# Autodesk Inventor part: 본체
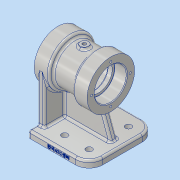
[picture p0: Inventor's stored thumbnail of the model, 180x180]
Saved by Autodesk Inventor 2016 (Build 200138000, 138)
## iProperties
Created: 2020-06
Part Number: 본체
Material: 알루미늄 6061
Document SubType Name: Modeling
Designer: 605-12
Density: 2.7 g/cm^3
Appearance: 알루미늄 - 평지
Mass: 724.958 g
Surface Area: 642.533 cm^2
Volume: 268.503 cm^3
Author: 605-12
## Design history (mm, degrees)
sketch "스케치1"
  geometry: L1 (-45, 49)-(45, 49); L2 (45, 49)-(45, -49); L3 (45, -49)-(-45, -49); L4 (-45, -49)-(-45, 49); L5 (-45, 49)-(45, -49); L6 (45, 49)-(-45, -49); 1 further point
  constraints: 12 end point, 2 midpoint, 2 parallel, 1 horizontal, 1 perpendicular
  dimensions: "d0" = 90 distance of L2.end L3.end; "d1" = 98 distance of L1.end L2.end
extrude "돌출1" new body sketch "스케치1" distance "d2" = 10; taper "d3" = 0 deg
sketch "스케치3"
  geometry: L1 (50, 80)-(-28, 80); L2 (-28, 80)-(-28, 115); L3 (-28, 115)-(-6, 115); L4 (-6, 115)-(-6, 109); L5 (-6, 109)-(28, 109); L6 (28, 109)-(28, 115); L7 (28, 115)-(50, 115); L8 (50, 115)-(50, 80); L9 (45, 0)-(45, 10) reference; L10 (50, 103.5)-(32, 103.5); L11 (32, 103.5)-(32, 100); L12 (32, 100)-(26, 100); L13 (26, 100)-(26, 103); L14 (26, 103)-(-4, 103); L15 (-4, 103)-(-4, 100); L16 (-4, 100)-(-10, 100); L17 (-10, 100)-(-10, 103.5); L18 (-10, 103.5)-(-28, 103.5); 3 further points
  constraints: 34 end point, 14 perpendicular, 4 point on line, 2 midpoint, 1 horizontal, 1 horizontal alignment, 1 vertical
  dimensions: "d4" = 5 distance from line of L9 L1.start; "d5" = 78 distance of L7.end L2.end; "d6" = 80 vertical distance of L9.start L1.start; "d7" = 22 distance of L6.end L7.end; "d8" = 22 distance of L2.end L3.end; "d9" = 70 diameter of L7 L1; "d10" = 18 distance of L17.end L18.end; "d11" = 18 distance of L10.start L10.end; "d12" = 30 distance of L13.end L14.end; "d13" = 6 distance of L11.end L12.end; "d14" = 47 diameter of L10 L1; "d15" = 46 diameter of L14 L1; "d16" = 40 diameter of L12 L1; "d17" = 47 diameter of L18 L1; "d18" = 58 diameter of L5 L1
revolve "회전1" sketch "스케치3" stored, may be unused: angle "d19" = 90 deg
node "작업 평면1"
sketch "스케치4"
  geometry: L1 (-50, 35)-(-50, -35) reference; C1 r 6 at (-11, 0); 1 further point
  constraints: 1 centre point, 1 horizontal alignment
  dimensions: "d21" = 12 diameter of C1; "d22" = 39 distance from line of L1 C1.centre
extrude "돌출2" join sketch "스케치4" stored distance "d23" = 10; taper "d24" = 0 deg
hole "구멍1" diameter "d27" = 5.188; stored, may be unused: countersink angle "d31" = 90 deg, drill point angle "d33" = 118 deg; dims "d25" = 10, "d26" = 10, "d28" = 12, "d29" = 4, "d30" = 2, "d32" = 16
sketch "스케치5"
  geometry: L1 (0, 0)-(28.5, 0); L2 (0, 0)-(28.5, 0); C1 r 20 at (0, 0) reference; 1 further point
  constraints: 4 end point, 2 horizontal, 1 collinear
  dimensions: "d34" = 28.5 distance of L1.start L1.end; "d35" = 0 distance between parallel lines of L1 L2 (derived)
hole "구멍2" sketch "스케치5" at (28.5, 0) diameter "d36" = 3.242; stored, may be unused: countersink angle "d40" = 90 deg, drill point angle "d42" = 118 deg; dims "d37" = 10, "d38" = 4, "d39" = 2, "d41" = 12
sketch "스케치6"
  geometry: L1 (0, 0)-(-28.5, 0); L2 (0, 0)-(28.5, 0); C1 r 35 at (0, 0) reference; 1 further point
  constraints: 4 end point, 2 horizontal, 1 collinear
  dimensions: "d46" = 28.5 distance of L1.start L1.end; "d47" = 180 deg angle of L1 L2 (derived)
hole "구멍3" sketch "스케치6" at (-28.5, 0) diameter "d48" = 3.242; stored, may be unused: countersink angle "d52" = 90 deg, drill point angle "d54" = 118 deg; dims "d49" = 10, "d50" = 4, "d51" = 2, "d53" = 12
sketch "스케치7"
  geometry: L1 (-45, -49)-(-45, 49) reference; L2 (-45, 35)-(-35, 35); L3 (-35, 35)-(-35, -35); L4 (-35, -35)-(-45, -35); L5 (-45, -35)-(-45, 35); 3 further points
  constraints: 8 end point, 2 midpoint, 2 parallel, 1 coincident, 1 horizontal, 1 perpendicular, 1 point on line
  dimensions: "d58" = 70 distance of L2.end L3.end; "d59" = 10 distance of L2.start L2.end
extrude "돌출3" join sketch "스케치7" stored distance "d60" = 10; taper "d61" = 0 deg
sketch "스케치8"
  geometry: L1 (-45, 10)-(45, 10) reference; L2 (-33, 10)-(-24.035, 34.631); 1 further point
  constraints: 2 end point, 1 point on line
  dimensions: "d63" = 12 distance of L2.start L1.start; "d64" = 70 deg angle of L1 L2
feature "리브1" sketch "스케치8" dims "d65" = 1, "d66" = 10, "d67" = 0, "d68" = 0, "d69" = 1, "d70" = 1
sketch "스케치9"
  geometry: L1 (-45, -49)-(-45, 49) reference; 5 further points
  constraints: 2 horizontal alignment, 2 vertical alignment
  dimensions: "d71" = 36 distance of point (25, 29) point (-11, 29); "d72" = 70 distance from line of point (25, 29) L1; "d73" = 58 distance of point (25, -29) point (25, 29); "d74" = 29 vertical distance of point (0, 0) point (25, 29)
hole "구멍4" sketch "스케치9" at (-11, -29), (25, -29), (25, 29), (-11, 29) diameter "d75" = 9; stored, may be unused: countersink angle "d79" = 90 deg, drill point angle "d81" = 118 deg; dims "d76" = 10, "d77" = 4, "d78" = 2, "d80" = 12
fillet "모깎기1" dims "d82" = 0.3, "d83" = 3
chamfer "모따기1" distance "d84" = 1; stored, may be unused: second distance "d85" = 2, angle "d86" = 45 deg
fillet "모깎기2" dims "d87" = 20
fillet "모깎기3" dims "d88" = 3
fillet "모깎기4" dims "d89" = 3
sketch "스케치11"
  geometry: L1 (67, 0)-(0, 0) reference; L2 (-3, 7)-(-3, 0) reference; 2 further points
  constraints: 1 other
  dimensions: "d90" = 4 distance from line of L1 point (42, 4); "d91" = 45 distance from line of point (42, 4) L2
feature "엠보싱1" sketch "스케치11" dims "d0" = 90, "d1" = 98, "d92" = 0.5, "d93" = 0
node "솔리드1"
pattern_circular "원형 패턴1" dims angle "d44" = 360 deg
pattern_circular "원형 패턴2" dims angle "d56" = 360 deg
other parameters: "d20" = 112
